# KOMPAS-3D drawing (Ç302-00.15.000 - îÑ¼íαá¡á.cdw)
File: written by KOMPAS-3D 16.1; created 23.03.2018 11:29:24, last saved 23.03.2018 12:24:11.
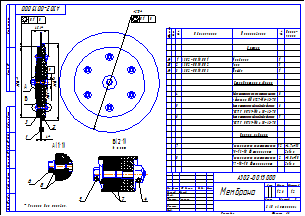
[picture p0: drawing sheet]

Sheet 1: A3, landscape

Title block, sheet 1: name: Мембрана; designation: А302-00.15.000; mass: 1,26; scale: 1:2; sheets: 1; organisation: ЗАО «Астерион»; sheet format: A3; stored path: \\192.168.87.28\Konstructor_doc\Мембранные насосы\Мембранный электропривод\А302-00.00.000 - ASTRA-302 (МЭ200)\Чертежи\А302-00.15.000 - Мембрана.cdw; drawn by: Милов; technical control: Лучихин

Views: Вид 1, Местный разрез 1, Вид:1, Выносной элемент 3, Выносной элемент 4, Выносной элемент А, Выносной элемент, Выносной элемент Б
Referenced files in Z:\Мембранные насосы\Мембранный электропривод\А302-00.00.000 - ASTRA-302 (МЭ200)\3Д\: А302-00.15.002 - Упор.m3d, А302-00.15.003 - Шайба.m3d, А302-00.15.001 - Мембрана.m3d, А302-00.15.001 - Мембрана.a3d
Referenced files in \\192.168.87.28\Konstructor_doc\Мембранные насосы\Мембранный электропривод\А302-00.00.000 - ASTRA-302 (МЭ200)\Чертежи\: А302-00.15.001 - Мембрана.cdw, А302-00.15.003 - Шайба.cdw, А302-00.15.002 - Упор.cdw
Referenced files: graphic.tdp
Referenced files in C:\Program Files\ASCON\KOMPAS-3D V16\Libs\PartLib\DATA\vault\Methods\Kompas\3D\: PLib_Bolt_1_ISO_1100.m3d
Referenced files in D:\3Д модели\Крепеж\: Гайка шестигранная самостопорящаяся с фланцем DIN 6927-M6 - A2-70.m3d
Referenced files in Z:\1 ПКИ 3D\РТИ\Кольца уплотнительные  плоские\: Кольцо плоское уплотнительное 5-13-10 Ф4.m3d, Кольцо плоское уплотнительное 7-18-10 Ф4.m3d
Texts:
  * Размеры для справок.
  Шайба
  Упор
  Болт с шестигранной головкой с фланцем
  ГОСТ Р  55739-М5 x 30-A2-70
  ГОСТ
  Нержавеющая сталь
  Гайка шестигранная самостопорящаяся
  с фланцем DIN 6927-M6-A2-70
  Гайка
  шестигранная
  самостопорящаяся
  фланцем
  DIN
  Кольцо плоское уплотнительное
  Кольцо плоское уплотнительное / 05-13-10 Фторопласт
  @2~4,7х@2~13S=1мм
  ГОСТ Р  55739-М8 x 30-A2-70
  Кольцо плоское уплотнительное / 07-18-10 Фторопласт
  @2~6,8х@2~18S=1мм
  Лит-Масса-Масштаб
  Материал-Предприятие
  Title Specification
  Body Specification ( left align )
  Body Specificaton ( centered )
  Поз.
  Кол.
  Приме-
  чание
  Таблица спецификации
  Болт с шестигранной головкой с фланцем ГОСТ Р 55739 - М5 x 30 - A2-70
  Гайка шестигранная самостопорящаяся с фланцем DIN 6927-M6 - A2-70
  Кольцо плоское уплотнительное 5-13-10 Ф4
  Болт с шестигранной головкой с фланцем ГОСТ Р 55739 - М8 x 30 - A2-70
  Кольцо плоское уплотнительное 7-18-10 Ф4
Dimensions and other numbers on the sheet: 214; 196; 1; 3; 2; 13,5; 45,1; 0,1; 4; 6; 8; 6 мест; 7; 5; 05-13-10 Фторопласт; 07-18-10 Фторопласт; 1:2; 1,26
